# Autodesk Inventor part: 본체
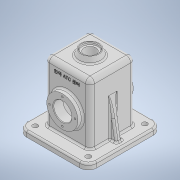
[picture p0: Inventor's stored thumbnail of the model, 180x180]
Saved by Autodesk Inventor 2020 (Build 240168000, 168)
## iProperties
Created: 2022-11
Part Number: 본체
Material: 일반
Document SubType Name: Modeling
Designer: USER
Density: 1 g/cm^3
Appearance: 기본값
Author: USER
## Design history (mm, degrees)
sketch "스케치1"
  geometry: L1 (62, -65)-(-62, -65); L2 (-62, -65)-(-62, 65); L3 (-62, 65)-(62, 65); L4 (62, 65)-(62, -65); L5 (62, -65)-(-62, 65); L6 (-62, -65)-(62, 65); 1 further point
  constraints: 12 end point, 2 midpoint, 2 parallel, 1 horizontal, 1 perpendicular
  dimensions: "d0" = 124 distance of L2.end L3.end; "d1" = 130 distance of L1.end L2.end
extrude "돌출1" new body sketch "스케치1" distance "d2" = 10; taper "d3" = 0 deg
fillet "모깎기1" dims "d4" = 15
sketch "스케치2"
  geometry: L1 (-40, 40)-(40, 40); L2 (40, 40)-(40, -40); L3 (40, -40)-(-40, -40); L4 (-40, -40)-(-40, 40); L5 (-40, 40)-(40, -40); L6 (40, 40)-(-40, -40); 1 further point
  constraints: 12 end point, 2 midpoint, 2 parallel, 1 horizontal, 1 perpendicular
  dimensions: "d5" = 80 distance of L2.end L3.end; "d6" = 80 distance of L1.end L2.end
extrude "돌출2" join sketch "스케치2" distance "d7" = 107; taper "d8" = 0 deg
sketch "스케치6"
  geometry: L1 (80, 0)-(0, 0) reference; L2 (40, 0)-(40, 45); C1 r 27.5 at (40, 45); 1 further point
  constraints: 2 end point, 1 centre point, 1 coincident, 1 midpoint, 1 vertical
  dimensions: "d18" = 45 distance of L2.start L2.end; "d19" = 55 diameter of C1
extrude "돌출6" join sketch "스케치6" distance "d20" = 9; taper "d21" = 0 deg
sketch "스케치7"
  geometry: 1 further point
sketch "스케치8"
  geometry: C1 r 27.5 at (0, 0) reference; C2 r 16 at (0, 0); 1 further point
  constraints: 1 centre point, 1 coincident
  dimensions: "d25" = 32 diameter of C2
extrude "돌출7" cut sketch "스케치8" extent not by distance; stored distance "d26" = 0; taper "d27" = 0 deg
chamfer "모따기2" distance "d28" = 1; stored, may be unused: second distance "d29" = 2, angle "d30" = 45 deg
sketch "스케치9"
  geometry: L1 (117, 40)-(117, -40) reference; L2 (117, 0)-(117, -20); L3 (117, -20)-(127, -16.36); L4 (117, -20)-(136.148, -20); L5 (117, 0)-(127, 0); L6 (127, 0)-(127, -16.36); L7 (117, -40)-(117, 40); L8 (117, 0)-(117, 20); L9 (117, 20)-(127, 16.36); L10 (127, 0)-(127, 16.36); 4 further points
  constraints: 18 end point, 5 symmetric about line, 2 horizontal, 2 point on line, 1 midpoint, 1 perpendicular
revolve "회전1" sketch "스케치9" stored, may be unused: angle "d34" = 90 deg
fillet "모깎기2" dims "d35" = 3
sketch "스케치10"
  geometry: C1 r 14 at (0, 0); 1 further point
  constraints: 1 centre point, 1 coincident
  dimensions: "d36" = 28 diameter of C1
extrude "돌출8" cut sketch "스케치10" distance "d37" = 4; taper "d38" = 0 deg
chamfer "모따기3" distance "d39" = 1; stored, may be unused: second distance "d40" = 2, angle "d41" = 45 deg
sketch "스케치11"
  geometry: C1 r 10.5 at (0, 0); 1 further point
  constraints: 1 centre point, 1 coincident
  dimensions: "d42" = 21 diameter of C1
extrude "돌출9" cut sketch "스케치11" distance "d43" = 32.5; taper "d44" = 0 deg
sketch "스케치12"
  geometry: L1 (32, 32)-(-32, 32); L2 (-32, 32)-(-32, -32); L3 (-32, -32)-(32, -32); L4 (32, -32)-(32, 32); L5 (32, 32)-(-32, -32); L6 (-32, 32)-(32, -32); 1 further point
  constraints: 12 end point, 2 midpoint, 2 parallel, 1 horizontal, 1 perpendicular
  dimensions: "d45" = 64 distance of L3.end L2.end; "d46" = 64 distance of L2.end L1.end
extrude "돌출10" cut sketch "스케치12" distance "d47" = 109; taper "d48" = 0 deg
sketch "스케치13" dims "d49" = 45
  geometry: L1 (0, 0)-(0, 22.5); C1 r 27.5 at (0, 0) reference; C2 r 16 at (0, 0) reference; 2 further points
  constraints: 2 end point, 1 coincident, 1 vertical, 1 vertical alignment, 2 other
hole "구멍1" sketch "스케치13" at (0, 22.5) diameter "d50" = 3.242; stored, may be unused: countersink angle "d54" = 82 deg, drill point angle "d56" = 118 deg; dims "d51" = 8, "d52" = 3.023, "d53" = 2, "d55" = 10
sketch "스케치14"
  geometry: C1 r 4.5 at (-47, 50); A1 r 15 centre (-47, 50) between (-47, 65) and (-62, 50) reference; 1 further point
  constraints: 1 centre point, 1 coincident
  dimensions: "d60" = 9 diameter of C1
extrude "돌출11" cut sketch "스케치14" extent not by distance; stored distance "d61" = 0; taper "d62" = 0 deg
sketch "스케치15"
  geometry: L1 (-62, 10)-(-47, 10); L2 (-62, 10)-(-62, 0); L3 (-62, 10)-(-52, 10); L4 (-52, 10)-(-44.415, 53.017); L5 (-44.415, 53.017)-(-40, 78.055); L6 (-40, 10)-(-40, 117); L7 (-47, 10)-(-40, 10); L8 (-42.5, 0)-(-51.5, 0) reference; 1 further point
  constraints: 14 end point, 2 point on line, 1 parallel
extrude "돌출12" join sketch "스케치15" stored distance "d65" = 10; taper "d66" = 0 deg
fillet "모깎기3" dims "d67" = 3
sketch "스케치16"
  geometry: L1 (47, 10)-(62, 10) reference; L2 (40, 10)-(40, 117) reference; L3 (47, 10)-(62, 10) reference; L4 (62, 10)-(52, 10); L5 (52, 10)-(37.717, 91.001); L6 (52, 10)-(134.251, 10); L7 (47, 10)-(40, 10); 3 further points
  constraints: 8 end point, 2 horizontal, 1 equal length, 1 point on line
  dimensions: "d68" = 10 distance of L1.end L4.end; "d69" = 100 deg angle of L6 L5
extrude "돌출13" join sketch "스케치16" stored distance "d70" = 10; taper "d71" = 0 deg
fillet "모깎기4" dims "d72" = 3
fillet "모깎기5" dims "d73" = 8
fillet "모깎기6" dims "d74" = 8
fillet "모깎기7" dims "d75" = 3
fillet "모깎기8" dims "d76" = 3
fillet "모깎기9" dims "d77" = 3
sketch "스케치17"
  geometry: L1 (8.314, -4)-(54.433, -4); L2 (54.433, -4)-(54.433, -10.004); L3 (54.433, -10.004)-(8.314, -10.004); L4 (8.314, -10.004)-(8.314, -4); L5 (72, -96)-(72, 0) reference; L6 (48.36, 18)-(15.64, 18) reference; 2 further points
  constraints: 2 other
  dimensions: "d80" = 40 distance from line of L5 point (32, -7); "d81" = 25 distance from line of L6 point (32, -7); "d82" = 3 distance from line of L1 point (32, -7); "d83" = 6.00407 distance between parallel lines of L3 L1; "d84" = 23.68594 distance from line of L4 point (32, -7); "d85" = 46.1194 distance between parallel lines of L2 L4
feature "엠보싱1" sketch "스케치17" dims "d86" = 0.5, "d87" = 0
node "솔리드1"
mirror "미러1"
pattern_circular "원형 패턴1" dims angle "d58" = 360 deg
mirror "미러2"
mirror "미러3"
mirror "미러4"
node "투영된 루프1"
feature "A9D066F2-1C7D-4E18-AEED-F7BC21143FA4" dims "d50" = 3.242, "d51" = 8, "d52" = 3.023, "d53" = 2, "d54" = 82 deg, "d55" = 10, "d56" = 118 deg
